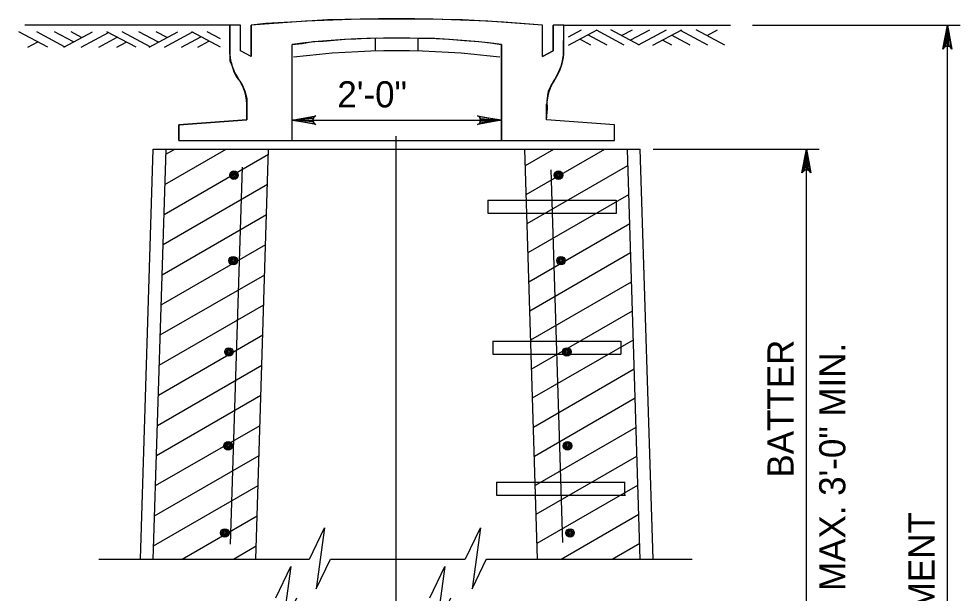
# Model space of a CAD drawing. Extents: x 0.9 to 8, y -0.9 to 9.3.
# Drawn here: x 5.186 to 7.346, y 3.453 to 4.771 of the extents above; entities that cross this region are included whole.
import ezdxf

# ---------------------------------------------------------------- set-up
doc = ezdxf.new("R2010")
doc.units = 0
for name, color, linetype in [('DETL-DIMS', 7, 'Continuous'), ('DETL-LINE', 7, 'Continuous'), ('DETL-NOTE', 7, 'Continuous'), ('DETL-PATT', 7, 'Continuous')]:
    doc.layers.add(name, color=color, linetype=linetype)

msp = doc.modelspace()

# ---------------------------------------------------------------- linework, layer by layer
at = {"layer": 'DETL-DIMS'}
for p, q in [((6.8694, 4.7566), (7.346, 4.7566)), ((7.3166, 1.8231), (7.3166, 4.7566)), ((5.8127, 4.5387), (6.2931, 4.5387)), ((6.0519, 1.8996), (6.0519, 4.5023)), ((6.6411, 4.4723), (7.0225, 4.4723)), ((6.9931, 3.2959), (6.9931, 4.4723))]:
    msp.add_line(p, q, dxfattribs=at)
for points in [[(7.3166, 4.7566), (7.3269, 4.7018), (7.324, 4.706), (7.3203, 4.7082), (7.3166, 4.7088), (7.313, 4.7082), (7.3093, 4.706), (7.3064, 4.7018), (7.3166, 4.7566), (7.3093, 4.706), (7.313, 4.7082), (7.3166, 4.7566), (7.3166, 4.7088), (7.3203, 4.7082), (7.3166, 4.7566), (7.324, 4.706)], [(5.8127, 4.5387), (5.8675, 4.549), (5.8633, 4.5461), (5.8611, 4.5424), (5.8605, 4.5387), (5.8611, 4.535), (5.8633, 4.5314), (5.8675, 4.5284), (5.8127, 4.5387), (5.8633, 4.5314), (5.8611, 4.535), (5.8127, 4.5387), (5.8605, 4.5387), (5.8611, 4.5424), (5.8127, 4.5387), (5.8633, 4.5461)], [(6.2931, 4.5387), (6.2383, 4.5284), (6.2425, 4.5314), (6.2447, 4.535), (6.2453, 4.5387), (6.2447, 4.5424), (6.2425, 4.5461), (6.2383, 4.549), (6.2931, 4.5387), (6.2425, 4.5461), (6.2447, 4.5424), (6.2931, 4.5387), (6.2453, 4.5387), (6.2447, 4.535), (6.2931, 4.5387), (6.2425, 4.5314)], [(6.9931, 4.4723), (7.0034, 4.4175), (7.0005, 4.4217), (6.9968, 4.4239), (6.9931, 4.4245), (6.9894, 4.4239), (6.9858, 4.4217), (6.9828, 4.4175), (6.9931, 4.4723), (6.9858, 4.4217), (6.9894, 4.4239), (6.9931, 4.4723), (6.9931, 4.4245), (6.9968, 4.4239), (6.9931, 4.4723), (7.0005, 4.4217)]]:
    msp.add_lwpolyline(points, dxfattribs=at)
at = {"layer": 'DETL-LINE'}
for p, q in [((5.6695, 4.7566), (5.199, 4.7566)), ((5.6695, 4.69), (5.6695, 4.7566)), ((5.6941, 4.6978), (5.6941, 4.7566)), ((5.7186, 4.6845), (5.7186, 4.7566)), ((6.3872, 4.6845), (6.3872, 4.7566)), ((6.4117, 4.6978), (6.4117, 4.7566)), ((6.4362, 4.69), (6.4362, 4.7566)), ((6.4362, 4.7566), (6.8186, 4.7566)), ((5.8127, 4.4919), (5.8127, 4.7125)), ((6.0039, 4.6975), (6.0039, 4.7269)), ((6.1019, 4.6975), (6.1019, 4.7269)), ((6.2931, 4.4919), (6.2931, 4.7125)), ((5.7186, 4.6845), (5.6941, 4.6978)), ((6.3872, 4.6845), (6.4117, 4.6978)), ((5.7088, 4.5395), (5.7088, 4.5752)), ((6.397, 4.5395), (6.397, 4.5752)), ((5.5529, 4.5283), (5.7088, 4.5395)), ((6.5529, 4.5283), (6.397, 4.5395)), ((5.5529, 4.4919), (5.5529, 4.5283)), ((6.5529, 4.4919), (6.5529, 4.5283)), ((5.4647, 3.5312), (5.4941, 4.4723)), ((5.4941, 4.4723), (6.6117, 4.4723)), ((5.5529, 4.4919), (6.5529, 4.4919)), ((5.7295, 3.5312), (5.7589, 4.4723)), ((6.3763, 3.5312), (6.3469, 4.4723)), ((6.6411, 3.5312), (6.6117, 4.4723)), ((5.4941, 3.5302), (5.5235, 4.4714)), ((6.6117, 3.5302), (6.5823, 4.4714)), ((5.6717, 3.5651), (5.6988, 4.4308)), ((6.434, 3.5691), (6.4072, 4.4248)), ((6.2622, 4.3547), (6.2622, 4.3253)), ((6.2622, 4.3547), (6.3506, 4.3547)), ((6.3506, 4.3547), (6.5565, 4.3547)), ((6.5563, 4.3547), (6.5563, 4.3253)), ((6.2622, 4.3253), (6.3515, 4.3253)), ((6.3515, 4.3253), (6.5575, 4.3253)), ((6.2733, 4.0312), (6.2733, 4.0017)), ((6.2733, 4.0312), (6.3607, 4.0312)), ((6.3607, 4.0312), (6.5667, 4.0312)), ((6.5674, 4.0312), (6.5674, 4.0017)), ((6.2733, 4.0017), (6.3616, 4.0017)), ((6.3616, 4.0017), (6.5676, 4.0017)), ((6.2816, 3.7076), (6.2816, 3.6782)), ((6.2816, 3.7076), (6.3708, 3.7076)), ((6.3708, 3.7076), (6.5768, 3.7076)), ((6.5757, 3.7076), (6.5757, 3.6782)), ((6.2816, 3.6782), (6.3717, 3.6782)), ((6.3717, 3.6782), (6.5777, 3.6782)), ((5.3692, 3.5312), (5.8519, 3.5312)), ((5.9005, 3.5312), (6.2102, 3.5312)), ((6.2587, 3.5312), (6.7312, 3.5312))]:
    msp.add_line(p, q, dxfattribs=at)
msp.add_lwpolyline([(5.6695, 4.7566), (5.6696, 4.6866), (5.6696, 4.675), (5.6749, 4.6623), (5.6791, 4.6497), (5.6854, 4.6371), (5.6927, 4.6286), (5.6991, 4.6181), (5.7043, 4.6055), (5.7085, 4.5886), (5.7088, 4.5395), (5.5529, 4.5283), (5.5529, 4.4919), (5.8127, 4.4919), (5.8127, 4.7125), (5.8359, 4.715), (5.8601, 4.7192), (5.8843, 4.7203), (5.9095, 4.7224), (5.9348, 4.7245), (5.959, 4.7255), (5.9842, 4.7266), (6.0063, 4.7276), (6.1019, 4.7266), (6.14, 4.7266), (6.1726, 4.7245), (6.2084, 4.7213), (6.241, 4.7192), (6.2684, 4.716), (6.2931, 4.7125), (6.2931, 4.4919), (6.5529, 4.4919), (6.5529, 4.5283), (6.397, 4.5395), (6.3988, 4.5655), (6.3978, 4.5823), (6.3999, 4.595), (6.4009, 4.6055), (6.4073, 4.6181), (6.4146, 4.6286), (6.4188, 4.6381), (6.4251, 4.6508), (6.4304, 4.6623), (6.4336, 4.675), (6.4357, 4.6876), (6.4362, 4.7566), (6.4117, 4.7566), (6.4117, 4.6978), (6.3872, 4.6845), (6.3872, 4.7566), (6.2978, 4.7634), (6.2042, 4.7687), (6.1137, 4.7708), (5.9727, 4.7708), (5.8937, 4.7687), (5.8232, 4.7645), (5.7527, 4.7603), (5.7186, 4.7566), (5.7186, 4.6845), (5.6941, 4.6978), (5.6941, 4.7566)], close=True, dxfattribs=at)
for points in [[(5.8524, 3.5313), (5.8874, 3.6027), (5.8683, 3.4628), (5.9009, 3.5313)], [(6.2105, 3.5316), (6.2455, 3.6031), (6.2264, 3.4632), (6.259, 3.5316)], [(5.7751, 3.4423), (5.81, 3.5138), (5.791, 3.3739), (5.8236, 3.4423)], [(6.1285, 3.4423), (6.1635, 3.5138), (6.1445, 3.3738), (6.177, 3.4423)]]:
    msp.add_lwpolyline(points, dxfattribs=at)
for centre, radius in [((5.6794, 4.4125), 0.0098), ((5.6794, 4.4125), 0.00735), ((5.6794, 4.4125), 0.0049), ((5.6794, 4.4125), 0.00245), ((6.4241, 4.4125), 0.0098), ((6.4241, 4.4125), 0.00735), ((6.4241, 4.4125), 0.0049), ((6.4241, 4.4125), 0.00245), ((5.6775, 4.2162), 0.0098), ((5.6775, 4.2162), 0.00735), ((5.6775, 4.2162), 0.0049), ((5.6775, 4.2162), 0.00245), ((6.4298, 4.2162), 0.0098), ((6.4298, 4.2162), 0.00735), ((6.4298, 4.2162), 0.0049), ((6.4298, 4.2162), 0.00245), ((5.6679, 4.0066), 0.0098), ((5.6679, 4.0066), 0.00735), ((5.6679, 4.0066), 0.0049), ((5.6679, 4.0066), 0.00245), ((6.4431, 4.0066), 0.0098), ((6.4431, 4.0066), 0.00735), ((6.4431, 4.0066), 0.0049), ((6.4431, 4.0066), 0.00245), ((5.666, 3.7912), 0.0098), ((5.666, 3.7912), 0.00735), ((5.666, 3.7912), 0.0049), ((5.666, 3.7912), 0.00245), ((6.445, 3.7912), 0.0098), ((6.445, 3.7912), 0.00735), ((6.445, 3.7912), 0.0049), ((6.445, 3.7912), 0.00245), ((5.6584, 3.5911), 0.0098), ((5.6584, 3.5911), 0.00735), ((5.6584, 3.5911), 0.0049), ((5.6584, 3.5911), 0.00245), ((6.4507, 3.5911), 0.0098), ((6.4507, 3.5911), 0.00735), ((6.4507, 3.5911), 0.0049), ((6.4507, 3.5911), 0.00245)]:
    msp.add_circle(centre, radius, dxfattribs=at)
for centre, radius, start, end in [((6.0529, 0.9636), 3.8078, 84.9628, 95.0372), ((6.0529, 2.7583), 1.969, 82.9929, 97.0071), ((5.7876, 4.6996), 0.1184, 184.6241, 212.5945), ((6.0529, 2.7583), 1.9395, 82.9929, 97.0071), ((6.3182, 4.6996), 0.1184, 327.4055, 355.3759)]:
    msp.add_arc(centre, radius, start, end, dxfattribs=at)
for centre, major_axis, start_param, end_param in [((5.6674, 4.5855), (0.014, -0.0676), 1.155753, 2.283479), ((6.4384, 4.5855), (-0.014, -0.0676), 3.999706, 5.127432)]:
    msp.add_ellipse(centre, major_axis=major_axis, ratio=0.578291, start_param=start_param, end_param=end_param, dxfattribs=at)
at = {"layer": 'DETL-PATT'}
for p, q in [((5.2518, 4.7061), (5.1856, 4.7417)), ((5.2907, 4.7071), (5.2266, 4.7417)), ((5.311, 4.7182), (5.2677, 4.7417)), ((5.2889, 4.7061), (5.3548, 4.7417)), ((5.3296, 4.7286), (5.3057, 4.7417)), ((5.3283, 4.7061), (5.391, 4.7399)), ((5.4546, 4.7061), (5.3879, 4.7417)), ((5.4869, 4.7072), (5.4228, 4.7417)), ((5.5059, 4.7175), (5.4612, 4.7417)), ((5.4846, 4.7061), (5.5505, 4.7418)), ((5.5257, 4.7282), (5.501, 4.7417)), ((5.52, 4.7061), (5.5836, 4.7406)), ((5.6481, 4.7061), (5.5823, 4.7417)), ((5.6481, 4.7251), (5.6176, 4.7417)), ((6.4468, 4.7297), (6.4772, 4.7462)), ((6.4468, 4.7107), (6.5126, 4.7462)), ((6.536, 4.7107), (6.4918, 4.7349)), ((6.5749, 4.7107), (6.5113, 4.7451)), ((6.6102, 4.7107), (6.5444, 4.7463)), ((6.5691, 4.7328), (6.5939, 4.7462)), ((6.589, 4.722), (6.6336, 4.7462)), ((6.608, 4.7118), (6.6721, 4.7462)), ((6.6403, 4.7107), (6.707, 4.7462)), ((6.726, 4.7107), (6.6836, 4.7338)), ((6.7666, 4.7107), (6.7039, 4.7445)), ((6.8059, 4.7107), (6.7401, 4.7462)), ((6.7653, 4.7331), (6.7891, 4.7462)), ((5.2063, 4.7061), (5.2289, 4.7184)), ((5.3689, 4.7061), (5.4113, 4.7292)), ((5.4104, 4.7061), (5.4321, 4.7181)), ((5.5589, 4.7061), (5.603, 4.7303)), ((5.5964, 4.7061), (5.622, 4.7202)), ((6.4984, 4.7107), (6.4728, 4.7247)), ((6.6844, 4.7107), (6.6628, 4.7226)), ((5.521, 4.3914), (5.6611, 4.4723)), ((5.5231, 4.4606), (5.5435, 4.4723)), ((6.3481, 4.4348), (6.4131, 4.4723)), ((6.3501, 4.368), (6.5308, 4.4723)), ((5.5188, 4.3222), (5.7585, 4.4607)), ((6.3522, 4.3013), (6.5835, 4.4348)), ((5.5166, 4.2531), (5.7564, 4.3915)), ((6.3543, 4.2346), (6.5856, 4.3681)), ((5.5145, 4.1839), (5.7542, 4.3223)), ((6.3564, 4.1679), (6.5876, 4.3014)), ((5.5123, 4.1147), (5.7521, 4.2531)), ((6.3585, 4.1012), (6.5897, 4.2347)), ((5.5102, 4.0456), (5.7499, 4.184)), ((6.3606, 4.0344), (6.5918, 4.1679)), ((5.508, 3.9764), (5.7477, 4.1148)), ((6.3627, 3.9677), (6.5939, 4.1012)), ((5.5058, 3.9072), (5.7456, 4.0456)), ((6.3647, 3.901), (6.596, 4.0345)), ((5.5037, 3.838), (5.7434, 3.9765)), ((6.3668, 3.8343), (6.5981, 3.9678)), ((5.5015, 3.7689), (5.7413, 3.9073)), ((6.3689, 3.7676), (6.6001, 3.9011)), ((5.4994, 3.6997), (5.7391, 3.8381)), ((6.371, 3.7008), (6.6022, 3.8343)), ((5.4972, 3.6305), (5.7369, 3.7689)), ((6.3731, 3.6341), (6.6043, 3.7676)), ((5.495, 3.5614), (5.7348, 3.6998)), ((6.3752, 3.5674), (6.6064, 3.7009)), ((5.5604, 3.5312), (5.7326, 3.6306)), ((6.43, 3.5312), (6.6085, 3.6342)), ((6.5477, 3.5312), (6.6106, 3.5675)), ((5.678, 3.5312), (5.7304, 3.5614))]:
    msp.add_line(p, q, dxfattribs=at)

# ---------------------------------------------------------------- texts
at = {"layer": 'DETL-NOTE'}
msp.add_text('2\'-0"', height=0.06, dxfattribs=at).set_placement((5.9166, 4.5681))
for s, p in [('BATTER', (6.9637, 3.7182)), ('4\'-0" MAX. 3\'-0" MIN.', (7.0825, 3.2758)), ('9\'-0" MIN. DEPTH PAYMENT', (7.2872, 2.5831))]:
    msp.add_text(s, height=0.06, rotation=90, dxfattribs=at).set_placement(p)

doc.saveas('drawing.dxf')
